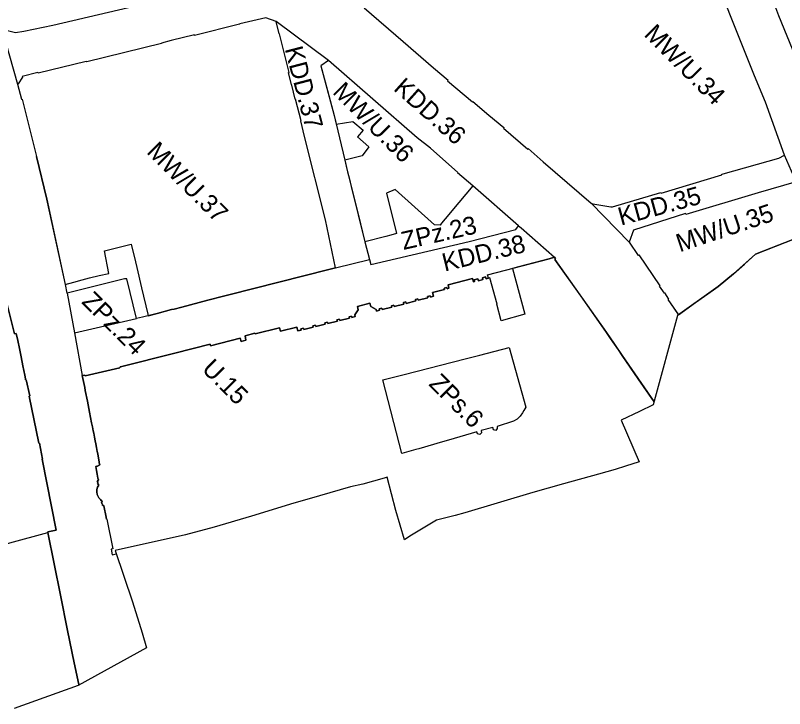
# Model space of a CAD drawing. Extents: x 7423835 to 7425280, y 5546086 to 5547600.
# Drawn here: x 7424338 to 7424593.5, y 5546110.1 to 5546340.4 of the extents above; entities that cross this region are included whole.
import ezdxf

# ---------------------------------------------------------------- set-up
doc = ezdxf.new("R2010")
doc.units = 0
for name, color, linetype in [('linie rozgraniczające', 7, 'Continuous'), ('nieprzekraczalne linie zabudowy', 7, 'Continuous'), ('obowiazujace linie zabudowy', 7, 'Continuous'), ('przeznaczenia terenów', 7, 'Continuous')]:
    doc.layers.add(name, color=color, linetype=linetype)

msp = doc.modelspace()

# ---------------------------------------------------------------- linework, layer by layer
at = {"layer": 'linie rozgraniczające'}
for p, q in [((7424333.41, 5546336.36), (7424338.71, 5546317.61)), ((7424442.04, 5546325.42), (7424424.6, 5546338.39)), ((7424597.34, 5546285.16), (7424593.44, 5546293.94)), ((7424541.85, 5546265.07), (7424529.29, 5546278.06)), ((7424444.28, 5546256.57), (7424455.56, 5546259.34)), ((7424357.58, 5546234.92), (7424360.18, 5546220.75)), ((7424359.01, 5546118.14), (7424359.08, 5546117.95))]:
    msp.add_line(p, q, dxfattribs=at)
for points in [[(7424595.52, 5546492.88), (7424562.11, 5546482.06), (7424541.11, 5546474.97), (7424539.74, 5546472.92), (7424541.62, 5546468.6), (7424546.51, 5546455.96), (7424549.64, 5546447.94), (7424561.93, 5546416.26), (7424565.58, 5546406.74), (7424576.21, 5546379.83), (7424577.6, 5546376.12), (7424580.47, 5546370.11), (7424584.82, 5546358.39), (7424587.04, 5546352.21), (7424588.52, 5546348.5), (7424591.51, 5546340.39), (7424598.75, 5546322.51)], [(7424329.68, 5546348.73), (7424333.41, 5546336.36), (7424335.31, 5546335.37), (7424338.04, 5546334.78), (7424340.75, 5546335.13), (7424350.4, 5546337.18), (7424412.55, 5546351.75), (7424415.01, 5546352.54), (7424417.37, 5546354.37), (7424418.62, 5546356.9), (7424418.49, 5546360.03), (7424406.49, 5546406.68), (7424405.05, 5546415.06), (7424405.06, 5546424.89), (7424402.17, 5546436.72)], [(7424552.44, 5546281.41), (7424572.67, 5546287.45), (7424572.62, 5546287.62), (7424573.12, 5546287.79), (7424591.59, 5546292.98), (7424593.44, 5546293.94), (7424587.14, 5546311.55), (7424583.54, 5546320.29), (7424575.79, 5546339.67), (7424571.69, 5546350.19), (7424566.51, 5546363.45), (7424564, 5546369.59), (7424564.15, 5546369.64), (7424561.54, 5546376.13)], [(7424453.79, 5546342.91), (7424466.82, 5546331.71), (7424476.92, 5546323.05), (7424481.72, 5546318.9), (7424481.57, 5546318.72), (7424489.81, 5546311.7), (7424489.93, 5546311.84), (7424495.2, 5546307.32), (7424500.2, 5546303.12), (7424500.19, 5546303.11), (7424500.08, 5546302.98), (7424508.17, 5546295.99), (7424508.3, 5546296.16), (7424513.28, 5546291.82), (7424529.29, 5546278.06), (7424529.8, 5546277.86), (7424535.74, 5546276.79), (7424536.29, 5546276.86), (7424552.39, 5546281.55), (7424552.44, 5546281.41)], [(7424444.28, 5546256.57), (7424441, 5546272.53), (7424434.04, 5546300.16), (7424432.77, 5546305.36), (7424432.92, 5546305.4), (7424431.03, 5546312.59), (7424430.87, 5546312.55), (7424429.76, 5546317.19), (7424429.74, 5546317.4), (7424428.75, 5546321.46), (7424428.89, 5546321.5), (7424425.73, 5546334.28), (7424425.6, 5546334.25), (7424424.6, 5546338.39), (7424421.15, 5546339.63), (7424412.49, 5546337.56), (7424412.39, 5546337.48)], [(7424412.39, 5546337.48), (7424397.49, 5546333.74), (7424397.45, 5546333.93), (7424389.73, 5546332.13), (7424389.76, 5546332.03), (7424386.49, 5546331.23), (7424386.53, 5546331.06), (7424361.74, 5546325.04), (7424361.49, 5546325.12), (7424345.49, 5546321.24), (7424345.45, 5546321.41), (7424340.25, 5546320.14), (7424340.3, 5546319.93), (7424338.92, 5546317.66), (7424338.71, 5546317.61), (7424339.98, 5546312.56), (7424340.18, 5546312.61), (7424344.94, 5546293.58)], [(7424505.11, 5546270.55), (7424489.95, 5546283.76), (7424484.86, 5546288.17), (7424484.95, 5546288.28), (7424475.85, 5546296.26), (7424471.47, 5546299.79), (7424442.04, 5546325.42), (7424439.42, 5546323.66), (7424443.83, 5546307.21), (7424447.4, 5546292.33)], [(7424444.28, 5546256.57), (7424442.08, 5546256.03), (7424425.49, 5546251.81), (7424408.9, 5546247.59), (7424407.05, 5546247.11), (7424401.89, 5546245.85), (7424393.22, 5546243.54), (7424390.68, 5546242.88), (7424389.81, 5546242.66), (7424385.02, 5546241.42), (7424380.22, 5546240.19), (7424378.18, 5546239.71), (7424375.03, 5546252.93), (7424374.21, 5546252.87), (7424355.14, 5546248.17), (7424354.59, 5546251.01), (7424348.46, 5546279.39), (7424344.94, 5546293.58)], [(7424447.4, 5546292.33), (7424448.33, 5546288.41), (7424449.57, 5546283.57), (7424454.01, 5546265.14), (7424455.56, 5546259.34), (7424456, 5546257.68), (7424488.7, 5546265.33), (7424504.19, 5546269.34), (7424505.11, 5546270.55)], [(7424603.65, 5546268.86), (7424597.34, 5546285.16), (7424584.77, 5546281.49), (7424560.64, 5546274.28), (7424560.54, 5546274.6), (7424543.27, 5546269.06), (7424541.85, 5546265.07), (7424544.85, 5546260.67), (7424545.11, 5546260.84), (7424552.01, 5546250.6), (7424551.86, 5546250.5), (7424553.46, 5546248.13), (7424553.61, 5546248.22), (7424554.98, 5546246.2), (7424554.72, 5546246.03), (7424557.89, 5546241.44)], [(7424489.95, 5546283.76), (7424485.33, 5546278.3), (7424480.71, 5546272.85), (7424479.54, 5546271.35)], [(7424479.54, 5546271.35), (7424479.06, 5546270.73), (7424477.15, 5546270.81), (7424464.18, 5546282.54), (7424461.27, 5546281.31), (7424464.58, 5546267.92), (7424462.65, 5546267.39)], [(7424505.11, 5546270.55), (7424505.97, 5546269.8), (7424511.5, 5546264.92), (7424517.02, 5546260.05)], [(7424603.65, 5546268.86), (7424583.81, 5546261.05), (7424576.53, 5546254.57), (7424571.44, 5546250.36), (7424569.93, 5546249.26), (7424557.93, 5546240.76), (7424549.86, 5546211.03), (7424545.3, 5546208.8), (7424539.23, 5546206), (7424545.19, 5546192.12), (7424540.62, 5546190.71), (7424537.19, 5546189.56), (7424531.63, 5546188.05), (7424520.1, 5546184.81), (7424509.81, 5546181.88), (7424487.3, 5546175.18), (7424484.1, 5546174.23), (7424477.89, 5546172.7), (7424469.05, 5546167.46), (7424467.22, 5546166.19), (7424464.34, 5546175.96), (7424461.49, 5546187.01), (7424460.5, 5546186.73), (7424453.36, 5546184.73), (7424449.33, 5546183.82), (7424435.59, 5546179.86), (7424430.44, 5546178.37), (7424416.4, 5546174.05), (7424404.05, 5546170.39), (7424394.47, 5546167.81), (7424371.09, 5546162.62), (7424376.88, 5546145.57), (7424380.05, 5546135.25), (7424381.51, 5546130.31), (7424358.85, 5546117.82), (7424337.57, 5546110.13)], [(7424462.65, 5546267.39), (7424461.03, 5546266.95), (7424454.01, 5546265.14)], [(7424330.83, 5546262.98), (7424330.85, 5546262.16), (7424330.78, 5546261.63), (7424331.94, 5546257.17), (7424334.47, 5546247.48), (7424337.68, 5546234.64), (7424338.27, 5546234.77), (7424338.75, 5546232.4), (7424339.32, 5546229.72), (7424339.89, 5546227.04), (7424340.5, 5546224), (7424341.1, 5546220.95), (7424341.32, 5546219.63), (7424341.36, 5546219.32), (7424341.6, 5546219.34), (7424342.73, 5546213.99), (7424342.58, 5546213.96), (7424345.8, 5546198.29), (7424345.95, 5546198.32), (7424347.03, 5546193.01), (7424346.88, 5546192.97), (7424351.54, 5546169.38), (7424348.75, 5546168.82), (7424348.79, 5546168.6)], [(7424390.99, 5546228.26), (7424402.65, 5546231.18), (7424402.77, 5546230.69), (7424412.65, 5546233.22), (7424412.96, 5546232.13), (7424414.56, 5546232.56), (7424414.27, 5546233.94), (7424417.56, 5546234.81), (7424417.61, 5546234.58), (7424425.74, 5546236.59), (7424426.01, 5546235.47), (7424431.5, 5546236.83), (7424431.81, 5546235.58), (7424432.94, 5546235.86), (7424432.82, 5546236.3), (7424433.65, 5546236.51), (7424433.76, 5546236.08), (7424433.76, 5546236.07), (7424436.91, 5546236.86), (7424436.8, 5546237.31), (7424437.62, 5546237.52), (7424437.74, 5546237.07), (7424440.9, 5546237.86), (7424440.79, 5546238.3), (7424441.61, 5546238.51), (7424441.73, 5546238.07), (7424444.92, 5546238.87), (7424444.8, 5546239.31), (7424445.62, 5546239.53), (7424445.74, 5546239.08), (7424448.96, 5546239.89), (7424448.84, 5546240.32), (7424449.66, 5546240.54), (7424449.78, 5546240.09), (7424450.84, 5546240.36), (7424450.71, 5546240.89), (7424451.85, 5546242.65), (7424451.57, 5546243.75), (7424455.75, 5546244.83), (7424456, 5546243.72), (7424457.84, 5546242.7), (7424457.96, 5546242.2), (7424458.97, 5546242.46), (7424458.86, 5546242.91), (7424459.68, 5546243.12), (7424459.79, 5546242.67), (7424462.99, 5546243.5), (7424462.88, 5546243.93), (7424463.7, 5546244.14), (7424463.81, 5546243.71), (7424467.01, 5546244.54), (7424466.89, 5546244.99), (7424467.71, 5546245.21), (7424467.83, 5546244.75), (7424470.96, 5546245.56), (7424470.85, 5546246.01), (7424471.67, 5546246.22), (7424471.79, 5546245.78), (7424475, 5546246.61), (7424474.89, 5546247.02), (7424475.71, 5546247.24), (7424475.82, 5546246.82), (7424476.87, 5546247.09), (7424476.54, 5546248.35), (7424480.56, 5546249.39), (7424480.44, 5546249.85), (7424481.26, 5546250.06), (7424481.38, 5546249.61), (7424481.99, 5546249.77), (7424481.69, 5546250.94), (7424489.83, 5546253.04), (7424490.13, 5546251.88), (7424490.52, 5546251.97), (7424490.37, 5546252.59), (7424491.62, 5546252.9), (7424491.77, 5546252.28), (7424493.25, 5546252.65), (7424493.09, 5546253.26), (7424494.18, 5546253.53), (7424494.33, 5546252.92), (7424495.15, 5546253.12), (7424494.84, 5546254.23), (7424515.32, 5546259.56), (7424517.02, 5546260.05), (7424517.34, 5546259.54), (7424517.22, 5546259.38), (7424534.36, 5546235.04), (7424536.99, 5546231.18), (7424539.56, 5546227.4), (7424550.12, 5546212)], [(7424355.14, 5546248.17), (7424357.58, 5546234.92), (7424378.18, 5546239.71)], [(7424557.89, 5546241.44), (7424558.03, 5546241.17), (7424558.19, 5546240.94)], [(7424361.06, 5546220.93), (7424361.1, 5546220.73), (7424372.68, 5546223.33), (7424372.68, 5546223.46), (7424372.73, 5546223.56), (7424372.81, 5546223.62), (7424372.87, 5546223.65), (7424372.86, 5546223.71), (7424390.99, 5546228.26)], [(7424368.4, 5546173.07), (7424368.4, 5546173.07), (7424368.21, 5546173.04), (7424368, 5546174.23), (7424367.97, 5546174.32), (7424367.45, 5546176.93), (7424367.32, 5546177.44), (7424366.78, 5546177.81), (7424366.89, 5546177.97), (7424366.7, 5546178.12), (7424366.79, 5546178.38), (7424366.6, 5546178.48), (7424366.75, 5546178.99), (7424366.47, 5546179.29), (7424366.19, 5546179.6), (7424365.94, 5546179.88), (7424365.69, 5546180.15), (7424365.11, 5546181.3), (7424365, 5546182.18), (7424365.07, 5546182.91), (7424365.29, 5546183.67), (7424365.71, 5546184.4), (7424365.28, 5546184.95), (7424365.46, 5546185.1), (7424365.25, 5546185.28), (7424365.34, 5546185.52), (7424365.19, 5546185.62), (7424365.53, 5546186.16), (7424365.41, 5546186.69), (7424365.16, 5546187.99), (7424364.91, 5546189.28), (7424364.78, 5546189.92), (7424364.64, 5546190.57), (7424364.99, 5546190.63), (7424365.21, 5546190.7), (7424365.47, 5546190.83), (7424365.67, 5546191.02), (7424365.81, 5546190.89), (7424365.97, 5546191.06), (7424366.01, 5546191.21), (7424365.96, 5546191.2), (7424365.77, 5546192.04), (7424365.31, 5546194.72), (7424365.15, 5546195.54), (7424364.91, 5546196.82), (7424364.66, 5546198.1), (7424364.46, 5546199.06), (7424364.22, 5546200.33), (7424363.98, 5546201.59), (7424363.98, 5546201.59), (7424363.82, 5546202.46), (7424363.57, 5546203.75), (7424363.31, 5546205.03), (7424362.95, 5546206.83), (7424362.59, 5546208.62), (7424362.59, 5546208.62), (7424361.89, 5546212.23), (7424361.19, 5546215.83), (7424360.99, 5546216.75), (7424360.38, 5546219.79), (7424360.18, 5546220.75), (7424361.06, 5546220.93)], [(7424368.4, 5546173.07), (7424370.33, 5546163.23), (7424369.75, 5546163.1), (7424370.15, 5546161.27), (7424371.45, 5546161.55)], [(7424324.88, 5546162.86), (7424326.81, 5546163.37), (7424335.07, 5546165.09), (7424335.13, 5546164.92), (7424336.09, 5546165.17), (7424348.79, 5546168.6)], [(7424348.79, 5546168.6), (7424352.94, 5546147.8), (7424355.27, 5546136.05), (7424357.52, 5546125.31), (7424359.01, 5546118.14)]]:
    msp.add_lwpolyline(points, dxfattribs=at)
msp.add_lwpolyline([(7424466.39, 5546194.86), (7424460.08, 5546219.33), (7424465.38, 5546220.69), (7424467.16, 5546221.14), (7424487.34, 5546226.35), (7424487.8, 5546226.47), (7424490.03, 5546227.02), (7424492.3, 5546227.6), (7424502, 5546230.12), (7424507.49, 5546210.25), (7424506.87, 5546209.16), (7424506.38, 5546208.37), (7424505.62, 5546207.27), (7424504.61, 5546206.28), (7424503.43, 5546205.61), (7424497.98, 5546203.89), (7424498.05, 5546203.16), (7424497.55, 5546202.57), (7424496.76, 5546202.76), (7424496.55, 5546203.56), (7424492.66, 5546202.48), (7424492.82, 5546201.71), (7424492.29, 5546201.21), (7424491.51, 5546201.37), (7424491.26, 5546202.09), (7424481.82, 5546199.29), (7424479.89, 5546198.76), (7424472, 5546196.48), (7424471.05, 5546196.2)], close=True, dxfattribs=at)
at = {"layer": 'nieprzekraczalne linie zabudowy'}
for points in [[(7424444.53, 5546304.29), (7424450.02, 5546305.14), (7424453.47, 5546302.3)], [(7424455.34, 5546296.8), (7424453.19, 5546293.71), (7424447.4, 5546292.33)], [(7424367.57, 5546262.16), (7424376.47, 5546264.46), (7424377.86, 5546258.54)], [(7424503.06, 5546256.37), (7424507.24, 5546241.2), (7424499.3, 5546239)]]:
    msp.add_lwpolyline(points, dxfattribs=at)
at = {"layer": 'obowiazujace linie zabudowy'}
msp.add_line((7424368.96, 5546254.65), (7424367.57, 5546262.16), dxfattribs=at)
for points in [[(7424552.44, 5546281.41), (7424572.67, 5546287.45), (7424572.62, 5546287.62), (7424573.12, 5546287.79), (7424591.59, 5546292.98), (7424593.44, 5546293.94), (7424587.14, 5546311.55), (7424583.54, 5546320.29), (7424575.79, 5546339.67), (7424571.69, 5546350.19), (7424566.51, 5546363.45), (7424564, 5546369.59), (7424564.15, 5546369.64), (7424561.54, 5546376.13)], [(7424453.79, 5546342.91), (7424466.82, 5546331.71), (7424476.92, 5546323.05), (7424481.72, 5546318.9), (7424481.57, 5546318.72), (7424489.81, 5546311.7), (7424489.93, 5546311.84), (7424495.2, 5546307.32), (7424500.2, 5546303.12), (7424500.19, 5546303.11), (7424500.08, 5546302.98), (7424508.17, 5546295.99), (7424508.3, 5546296.16), (7424513.28, 5546291.82), (7424529.29, 5546278.06), (7424529.8, 5546277.86), (7424535.74, 5546276.79), (7424536.29, 5546276.86), (7424552.39, 5546281.55), (7424552.44, 5546281.41)], [(7424444.28, 5546256.57), (7424441, 5546272.53), (7424434.04, 5546300.16), (7424432.77, 5546305.36), (7424432.92, 5546305.4), (7424431.03, 5546312.59), (7424430.87, 5546312.55), (7424429.76, 5546317.19), (7424429.74, 5546317.4), (7424428.75, 5546321.46), (7424428.89, 5546321.5), (7424425.73, 5546334.28), (7424425.6, 5546334.25), (7424424.6, 5546338.39), (7424421.15, 5546339.63), (7424412.49, 5546337.56), (7424412.39, 5546337.48)], [(7424412.39, 5546337.48), (7424397.49, 5546333.74), (7424397.45, 5546333.93), (7424389.73, 5546332.13), (7424389.76, 5546332.03), (7424386.49, 5546331.23), (7424386.53, 5546331.06), (7424361.74, 5546325.04), (7424361.49, 5546325.12), (7424345.49, 5546321.24), (7424345.45, 5546321.41), (7424340.25, 5546320.14), (7424340.3, 5546319.93), (7424338.92, 5546317.66), (7424338.71, 5546317.61), (7424339.98, 5546312.56), (7424340.18, 5546312.61), (7424344.94, 5546293.58)], [(7424442.04, 5546325.42), (7424439.42, 5546323.66), (7424441.62, 5546315.44), (7424443.83, 5546307.21), (7424444.53, 5546304.29)], [(7424489.95, 5546283.76), (7424484.86, 5546288.17), (7424484.95, 5546288.28), (7424475.85, 5546296.26), (7424471.47, 5546299.79), (7424442.04, 5546325.42)], [(7424453.47, 5546302.3), (7424451.59, 5546300.02), (7424455.34, 5546296.8)], [(7424344.94, 5546293.58), (7424348.46, 5546279.39), (7424354.54, 5546250.99), (7424357.37, 5546251.79), (7424360.15, 5546252.58), (7424362.59, 5546253.27), (7424365.78, 5546253.96), (7424368.96, 5546254.65)], [(7424447.4, 5546292.33), (7424447.87, 5546290.37), (7424448.33, 5546288.41), (7424448.95, 5546285.99), (7424449.57, 5546283.57), (7424451.79, 5546274.36), (7424454.01, 5546265.14)], [(7424603.65, 5546268.86), (7424597.34, 5546285.16), (7424584.77, 5546281.49), (7424560.64, 5546274.28), (7424560.54, 5546274.6), (7424543.27, 5546269.06), (7424541.85, 5546265.07), (7424544.85, 5546260.67), (7424545.11, 5546260.84), (7424552.01, 5546250.6), (7424551.86, 5546250.5), (7424553.46, 5546248.13), (7424553.61, 5546248.22), (7424554.98, 5546246.2), (7424554.72, 5546246.03), (7424558.22, 5546240.96)], [(7424558.22, 5546240.96), (7424563.93, 5546245.01), (7424569.93, 5546249.26), (7424571.44, 5546250.36), (7424573.99, 5546252.46), (7424576.53, 5546254.57), (7424580.17, 5546257.81), (7424583.81, 5546261.05), (7424593.73, 5546264.96), (7424603.65, 5546268.86)], [(7424348.79, 5546168.6), (7424348.75, 5546168.82), (7424351.54, 5546169.38), (7424346.88, 5546192.97), (7424347.03, 5546193.01), (7424345.95, 5546198.32), (7424345.8, 5546198.29), (7424342.58, 5546213.96), (7424342.73, 5546213.99), (7424341.6, 5546219.34), (7424341.36, 5546219.32), (7424341.32, 5546219.63), (7424341.1, 5546220.95), (7424340.5, 5546224), (7424339.89, 5546227.04), (7424339.32, 5546229.72), (7424338.75, 5546232.4), (7424338.27, 5546234.77), (7424337.68, 5546234.64), (7424334.47, 5546247.48), (7424331.94, 5546257.17), (7424330.78, 5546261.63), (7424330.85, 5546262.16), (7424330.83, 5546262.98)], [(7424550.12, 5546212), (7424544.84, 5546219.7), (7424539.56, 5546227.4), (7424538.28, 5546229.29), (7424536.99, 5546231.18), (7424535.68, 5546233.11), (7424534.36, 5546235.04), (7424525.79, 5546247.21), (7424517.22, 5546259.38), (7424517.34, 5546259.54), (7424517.02, 5546260.05), (7424515.32, 5546259.56), (7424505.08, 5546256.9), (7424503.06, 5546256.37)], [(7424377.86, 5546258.54), (7424378.3, 5546256.67), (7424379.89, 5546249.88), (7424381.92, 5546241.21), (7424382.05, 5546240.66)], [(7424382.05, 5546240.66), (7424385.02, 5546241.42), (7424389.81, 5546242.66), (7424390.68, 5546242.88), (7424393.22, 5546243.54), (7424401.89, 5546245.85), (7424407.05, 5546247.11), (7424408.9, 5546247.59), (7424425.49, 5546251.81), (7424442.08, 5546256.03), (7424444.28, 5546256.57)], [(7424499.3, 5546239), (7424497.87, 5546244.45), (7424498.03, 5546244.51), (7424495.62, 5546253.24), (7424495.15, 5546253.12), (7424494.33, 5546252.92), (7424494.18, 5546253.53), (7424493.09, 5546253.26), (7424493.25, 5546252.65), (7424491.77, 5546252.28), (7424491.62, 5546252.9), (7424490.37, 5546252.59), (7424490.52, 5546251.97), (7424490.13, 5546251.88), (7424489.83, 5546253.04), (7424481.69, 5546250.94), (7424481.99, 5546249.77), (7424481.38, 5546249.61), (7424481.26, 5546250.06), (7424480.44, 5546249.85), (7424480.56, 5546249.39), (7424476.54, 5546248.35), (7424476.87, 5546247.09), (7424475.82, 5546246.82), (7424475.71, 5546247.24), (7424474.89, 5546247.02), (7424475, 5546246.61), (7424471.79, 5546245.78), (7424471.67, 5546246.22), (7424470.85, 5546246.01), (7424470.96, 5546245.56), (7424467.83, 5546244.75), (7424467.71, 5546245.21), (7424466.89, 5546244.99), (7424467.01, 5546244.54), (7424463.81, 5546243.71), (7424463.7, 5546244.14), (7424462.88, 5546243.93), (7424462.99, 5546243.5), (7424459.79, 5546242.67), (7424459.68, 5546243.12), (7424458.86, 5546242.91), (7424458.97, 5546242.46), (7424457.96, 5546242.2), (7424457.84, 5546242.7), (7424456, 5546243.72), (7424455.75, 5546244.83), (7424451.57, 5546243.75), (7424451.85, 5546242.65), (7424450.71, 5546240.89), (7424450.84, 5546240.36), (7424449.78, 5546240.09), (7424449.66, 5546240.54), (7424448.84, 5546240.32), (7424448.96, 5546239.89), (7424445.74, 5546239.08), (7424445.62, 5546239.53), (7424444.8, 5546239.31), (7424444.92, 5546238.87), (7424441.73, 5546238.07), (7424441.61, 5546238.51), (7424440.79, 5546238.3), (7424440.9, 5546237.86), (7424437.74, 5546237.07), (7424437.62, 5546237.52), (7424436.8, 5546237.31), (7424436.91, 5546236.86), (7424433.76, 5546236.07), (7424433.76, 5546236.08), (7424433.65, 5546236.51), (7424432.82, 5546236.3), (7424432.94, 5546235.86), (7424431.81, 5546235.58), (7424431.5, 5546236.83), (7424426.01, 5546235.47), (7424425.74, 5546236.59), (7424417.61, 5546234.58), (7424417.56, 5546234.81), (7424414.27, 5546233.94), (7424414.56, 5546232.56), (7424412.96, 5546232.13), (7424412.65, 5546233.22), (7424402.77, 5546230.69), (7424402.65, 5546231.18), (7424390.99, 5546228.26)], [(7424390.99, 5546228.26), (7424372.86, 5546223.71), (7424372.87, 5546223.65), (7424372.81, 5546223.62), (7424372.73, 5546223.56), (7424372.68, 5546223.46), (7424372.68, 5546223.33), (7424361.1, 5546220.73), (7424361.06, 5546220.93)], [(7424361.06, 5546220.93), (7424360.18, 5546220.75), (7424360.38, 5546219.79), (7424360.99, 5546216.75), (7424361.19, 5546215.83), (7424361.89, 5546212.23), (7424362.59, 5546208.62), (7424362.59, 5546208.62), (7424362.95, 5546206.83), (7424363.31, 5546205.03), (7424363.57, 5546203.75), (7424363.82, 5546202.46), (7424363.98, 5546201.59), (7424363.98, 5546201.59), (7424364.22, 5546200.33), (7424364.46, 5546199.06), (7424364.66, 5546198.1), (7424364.91, 5546196.82), (7424365.15, 5546195.54), (7424365.31, 5546194.72), (7424365.77, 5546192.04), (7424365.96, 5546191.2), (7424366.01, 5546191.21), (7424365.97, 5546191.06), (7424365.81, 5546190.89), (7424365.67, 5546191.02), (7424365.47, 5546190.83), (7424365.21, 5546190.7), (7424364.99, 5546190.63), (7424364.64, 5546190.57), (7424364.78, 5546189.92), (7424364.91, 5546189.28), (7424365.16, 5546187.99), (7424365.41, 5546186.69), (7424365.53, 5546186.16), (7424365.19, 5546185.62), (7424365.34, 5546185.52), (7424365.25, 5546185.28), (7424365.46, 5546185.1), (7424365.28, 5546184.95), (7424365.71, 5546184.4), (7424365.29, 5546183.67), (7424365.07, 5546182.91), (7424365, 5546182.18), (7424365.11, 5546181.3), (7424365.69, 5546180.15), (7424365.94, 5546179.88), (7424366.19, 5546179.6), (7424366.47, 5546179.29), (7424366.75, 5546178.99), (7424366.6, 5546178.48), (7424366.79, 5546178.38), (7424366.7, 5546178.12), (7424366.89, 5546177.97), (7424366.78, 5546177.81), (7424367.32, 5546177.44), (7424367.45, 5546176.93), (7424367.97, 5546174.32), (7424368, 5546174.23), (7424368.21, 5546173.04), (7424368.4, 5546173.07), (7424368.4, 5546173.07)], [(7424368.4, 5546173.07), (7424370.33, 5546163.23), (7424369.75, 5546163.1), (7424370.15, 5546161.27), (7424371.45, 5546161.55)], [(7424359.01, 5546118.14), (7424357.52, 5546125.31), (7424355.27, 5546136.05), (7424352.94, 5546147.8), (7424348.79, 5546168.6)]]:
    msp.add_lwpolyline(points, dxfattribs=at)

# ---------------------------------------------------------------- texts
at = {"layer": 'przeznaczenia terenów'}
for s, rotation, p in [('MW/U.34', 314.9764, (7424546.5, 5546333.81)), ('KDD.37', 284.6187, (7424427.42, 5546329.32)), ('MW/U.36', 314.9764, (7424443.04, 5546314.67)), ('KDD.36', 318.2499, (7424463.28, 5546315.74)), ('MW/U.37', 314.9764, (7424381.28, 5546294.79)), ('KDD.35', 15.3093, (7424539.12, 5546270.56)), ('MW/U.35', 18.5089, (7424558.67, 5546261.71)), ('ZPz.23', 12.7498, (7424466.89, 5546262.48)), ('KDD.38', 13.63, (7424480.56, 5546255.3)), ('ZPz.24', 314.9764, (7424359.69, 5546245.03)), ('U.15', 314.9764, (7424399.61, 5546222.6)), ('ZPs.6', 314.9764, (7424475.01, 5546217.72))]:
    msp.add_text(s, height=6, rotation=rotation, dxfattribs=at).set_placement(p)

doc.saveas('drawing.dxf')
